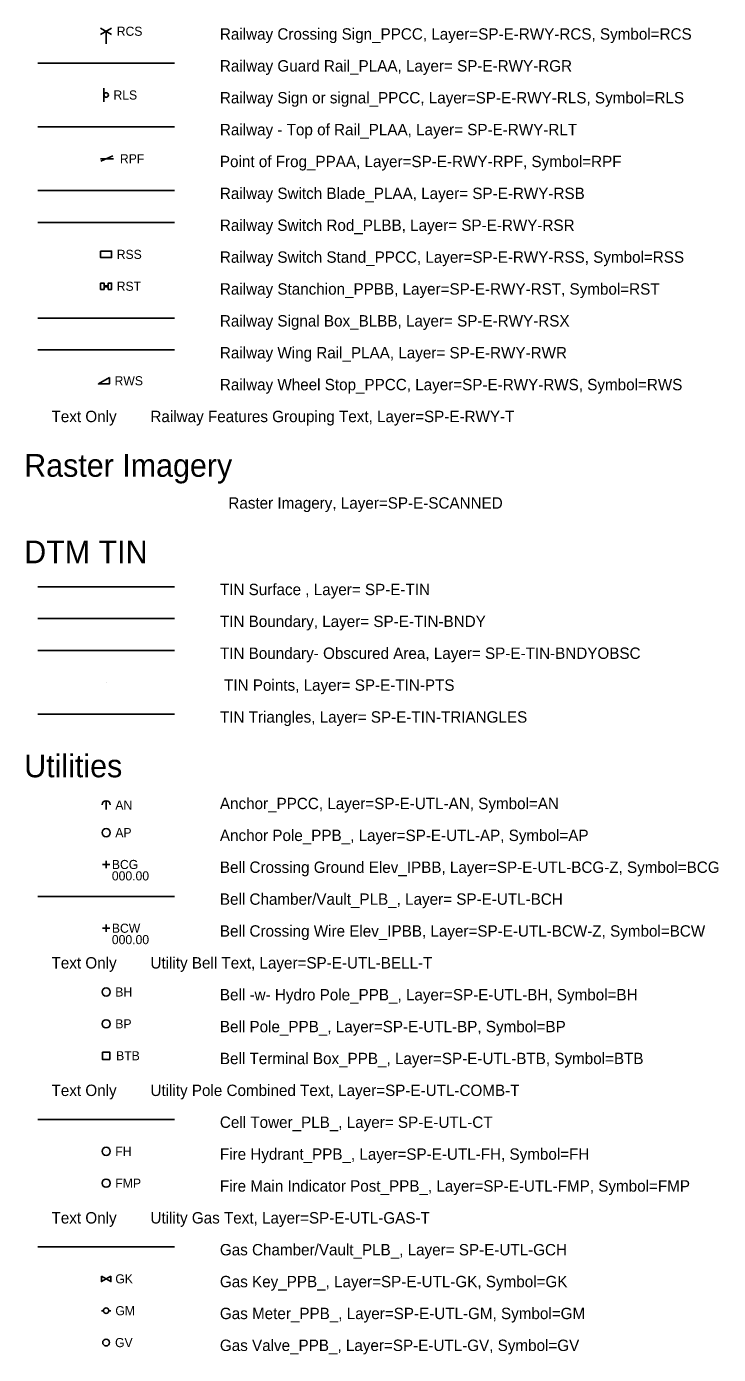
# Model space of a CAD drawing. Extents: x 500528 to 502626, y 4210261 to 4212624.
# Drawn here: x 501384.1 to 501536.1, y 4211147 to 4211438.6 of the extents above; entities that cross this region are included whole.
import ezdxf

# ---------------------------------------------------------------- set-up
doc = ezdxf.new("R2010")
doc.units = 0
for name, color, linetype in [('Default', 7, 'Continuous'), ('SP-E-RWY-RCS', 7, 'Continuous'), ('SP-E-RWY-RGR', 7, 'Continuous'), ('SP-E-RWY-RLS', 7, 'Continuous'), ('SP-E-RWY-RLT', 7, 'Continuous'), ('SP-E-RWY-RPF', 7, 'Continuous'), ('SP-E-RWY-RSB', 7, 'Continuous'), ('SP-E-RWY-RSR', 7, 'Continuous'), ('SP-E-RWY-RSS', 7, 'Continuous'), ('SP-E-RWY-RST', 7, 'Continuous'), ('SP-E-RWY-RSX', 7, 'Continuous'), ('SP-E-RWY-RWR', 7, 'Continuous'), ('SP-E-RWY-RWS', 7, 'Continuous'), ('SP-E-RWY-T', 7, 'Continuous'), ('SP-E-SCANNED', 7, 'Continuous'), ('SP-E-TIN', 7, 'Continuous'), ('SP-E-TIN-BNDY', 7, 'Continuous'), ('SP-E-TIN-BNDYOBSC', 7, 'Continuous'), ('SP-E-TIN-PTS', 7, 'Continuous'), ('SP-E-TIN-TRIANGLES', 7, 'Continuous'), ('SP-E-UTL-AN', 7, 'Continuous'), ('SP-E-UTL-AP', 7, 'Continuous'), ('SP-E-UTL-BCG-Z', 7, 'Continuous'), ('SP-E-UTL-BCH', 7, 'Continuous'), ('SP-E-UTL-BCW-Z', 7, 'Continuous'), ('SP-E-UTL-BELL-T', 7, 'Continuous'), ('SP-E-UTL-BH', 7, 'Continuous'), ('SP-E-UTL-BP', 7, 'Continuous'), ('SP-E-UTL-BTB', 7, 'Continuous'), ('SP-E-UTL-COMB-T', 7, 'Continuous'), ('SP-E-UTL-CT', 7, 'Continuous'), ('SP-E-UTL-FH', 7, 'Continuous'), ('SP-E-UTL-FMP', 7, 'Continuous'), ('SP-E-UTL-GAS-T', 7, 'Continuous'), ('SP-E-UTL-GCH', 7, 'Continuous'), ('SP-E-UTL-GK', 7, 'Continuous'), ('SP-E-UTL-GM', 7, 'Continuous'), ('SP-E-UTL-GV', 7, 'Continuous'), ('SP-E-UTL-T', 7, 'Continuous')]:
    doc.layers.add(name, color=color, linetype=linetype)

# ---------------------------------------------------------------- blocks, each defined once
blk = doc.blocks.new('RCS')
at = {"layer": 'SP-E-RWY-RCS'}
for points in [[(-0.121, -0.07), (0.121, 0.07)], [(0.121, -0.07), (-0.121, 0.07)], [(0, 0), (0, -0.28)], [(0, 0), (0, 0)]]:
    blk.add_lwpolyline(points, dxfattribs=at)
at = {"layer": 'SP-E-RWY-T'}
blk.add_text('RCS', height=0.2, dxfattribs=at).set_placement((0.233, -0.1))
blk = doc.blocks.new('RLS')
at = {"layer": 'SP-E-RWY-RLS'}
for points in [[(-0.05, -0.15), (-0.05, 0.15)], [(0, 0), (0, 0)]]:
    blk.add_lwpolyline(points, dxfattribs=at)
blk.add_circle((0, 0), 0.0495, dxfattribs=at)
at = {"layer": 'SP-E-RWY-T'}
blk.add_text('RLS', height=0.2, dxfattribs=at).set_placement((0.161, -0.1))
blk = doc.blocks.new('RPF')
at = {"layer": 'SP-E-RWY-RPF'}
blk.add_line((-0.125, 0), (0.161, 0), dxfattribs=at)
blk.add_lwpolyline([(-0.114, -0.05), (0.148, 0.065)], dxfattribs=at)
at = {"layer": 'SP-E-RWY-T'}
blk.add_text('RPF', height=0.2, dxfattribs=at).set_placement((0.303, -0.1))
blk = doc.blocks.new('RSS')
at = {"layer": 'SP-E-RWY-RSS'}
blk.add_lwpolyline([(-0.121, 0.07), (-0.121, -0.07), (0.121, -0.07), (0.121, 0.07), (-0.121, 0.07)], dxfattribs=at)
at = {"layer": 'SP-E-RWY-T'}
blk.add_text('RSS', height=0.2, dxfattribs=at).set_placement((0.233, -0.1))
blk = doc.blocks.new('RST')
at = {"layer": 'SP-E-RWY-RST'}
blk.add_lwpolyline([(-0.121, 0.07), (-0.121, -0.07), (-0.046, -0.07), (-0.046, -0.01), (0.046, -0.01), (0.046, -0.07), (0.121, -0.07), (0.121, 0.07), (0.046, 0.07), (0.046, 0.01), (-0.046, 0.01), (-0.046, 0.07), (-0.121, 0.07)], dxfattribs=at)
at = {"layer": 'SP-E-RWY-T'}
blk.add_text('RST', height=0.2, dxfattribs=at).set_placement((0.233, -0.1))
blk = doc.blocks.new('RWS')
at = {"layer": 'SP-E-RWY-RWS'}
blk.add_lwpolyline([(0.073, 0.094), (-0.169, -0.046), (0.073, -0.046), (0.073, 0.094)], dxfattribs=at)
at = {"layer": 'SP-E-RWY-T'}
blk.add_text('RWS', height=0.2, dxfattribs=at).set_placement((0.185, -0.076))
blk = doc.blocks.new('POINT_DISPLAY')
at = {"layer": 'Default'}
blk.add_line((0, 0), (0, 0), dxfattribs=at)
blk = doc.blocks.new('AN')
at = {"layer": 'SP-E-UTL-AN'}
blk.add_lwpolyline([(0, -0.19), (0, 0)], dxfattribs=at)
blk.add_arc((0, -0.09), 0.09, 360, 180, dxfattribs=at)
at = {"layer": 'SP-E-UTL-T'}
blk.add_text('AN', height=0.2, dxfattribs=at).set_placement((0.202, -0.195))
blk = doc.blocks.new('AP')
at = {"layer": 'SP-E-UTL-AP'}
blk.add_lwpolyline([(0, 0), (0, 0)], dxfattribs=at)
blk.add_circle((0, 0), 0.09, dxfattribs=at)
at = {"layer": 'SP-E-UTL-T'}
blk.add_text('AP', height=0.2, dxfattribs=at).set_placement((0.202, -0.1))
blk = doc.blocks.new('BCG')
at = {"layer": 'SP-E-UTL-BCG-Z'}
for points in [[(-0.08, 0), (0.08, 0)], [(0, -0.08), (0, 0.08)]]:
    blk.add_lwpolyline(points, dxfattribs=at)
at = {"layer": 'SP-E-UTL-BELL-T'}
for s, p in [('BCG', (0.126, -0.1)), ('000.00', (0.126, -0.35))]:
    blk.add_text(s, height=0.2, dxfattribs=at).set_placement(p)
blk = doc.blocks.new('BCW')
at = {"layer": 'SP-E-UTL-BCW-Z'}
for points in [[(-0.08, 0), (0.08, 0)], [(0, -0.08), (0, 0.08)]]:
    blk.add_lwpolyline(points, dxfattribs=at)
at = {"layer": 'SP-E-UTL-BELL-T'}
for s, p in [('BCW', (0.126, -0.1)), ('000.00', (0.126, -0.35))]:
    blk.add_text(s, height=0.2, dxfattribs=at).set_placement(p)
blk = doc.blocks.new('BH')
at = {"layer": 'SP-E-UTL-BH'}
blk.add_lwpolyline([(0, 0), (0, 0)], dxfattribs=at)
blk.add_circle((0, 0), 0.09, dxfattribs=at)
at = {"layer": 'SP-E-UTL-COMB-T'}
blk.add_text('BH', height=0.2, dxfattribs=at).set_placement((0.202, -0.1))
blk = doc.blocks.new('BP')
at = {"layer": 'SP-E-UTL-BP'}
blk.add_lwpolyline([(0, 0), (0, 0)], dxfattribs=at)
blk.add_circle((0, 0), 0.09, dxfattribs=at)
at = {"layer": 'SP-E-UTL-BELL-T'}
blk.add_text('BP', height=0.2, dxfattribs=at).set_placement((0.202, -0.1))
blk = doc.blocks.new('BTB')
at = {"layer": 'SP-E-UTL-BTB'}
for points in [[(-0.08, 0.08), (-0.08, -0.08), (0.08, -0.08), (0.08, 0.08), (-0.08, 0.08)], [(0, 0), (0, 0)]]:
    blk.add_lwpolyline(points, dxfattribs=at)
at = {"layer": 'SP-E-UTL-BELL-T'}
blk.add_text('BTB', height=0.2, dxfattribs=at).set_placement((0.22, -0.1))
blk = doc.blocks.new('FH')
at = {"layer": 'SP-E-UTL-FH'}
blk.add_lwpolyline([(0, 0), (0, 0)], dxfattribs=at)
blk.add_circle((0, 0), 0.09, dxfattribs=at)
at = {"layer": 'SP-E-UTL-T'}
blk.add_text('FH', height=0.2, dxfattribs=at).set_placement((0.202, -0.1))
blk = doc.blocks.new('FMP')
at = {"layer": 'SP-E-UTL-FMP'}
blk.add_lwpolyline([(0, 0), (0, 0)], dxfattribs=at)
blk.add_circle((0, 0), 0.09, dxfattribs=at)
at = {"layer": 'SP-E-UTL-T'}
blk.add_text('FMP', height=0.2, dxfattribs=at).set_placement((0.202, -0.1))
blk = doc.blocks.new('GK')
at = {"layer": 'SP-E-UTL-GK'}
for points in [[(-0.104, 0.06), (-0.104, -0.06), (0, 0), (-0.104, 0.06)], [(0.104, 0.06), (0.104, -0.06), (0, 0), (0.104, 0.06)]]:
    blk.add_lwpolyline(points, dxfattribs=at)
at = {"layer": 'SP-E-UTL-GAS-T'}
blk.add_text('GK', height=0.2, dxfattribs=at).set_placement((0.202, -0.1))
blk = doc.blocks.new('GM')
at = {"layer": 'SP-E-UTL-GM'}
for p, q in [((-0.06, 0), (-0.104, 0)), ((0.104, 0), (0.06, 0))]:
    blk.add_line(p, q, dxfattribs=at)
blk.add_circle((0, 0), 0.06, dxfattribs=at)
at = {"layer": 'SP-E-UTL-GAS-T'}
blk.add_text('GM', height=0.2, dxfattribs=at).set_placement((0.202, -0.1))
blk = doc.blocks.new('GV')
at = {"layer": 'SP-E-UTL-GV'}
blk.add_lwpolyline([(0, 0), (0, 0)], dxfattribs=at)
blk.add_circle((0, 0), 0.075, dxfattribs=at)
at = {"layer": 'SP-E-UTL-GAS-T'}
blk.add_text('GV', height=0.2, dxfattribs=at).set_placement((0.196, -0.1))

msp = doc.modelspace()

# ---------------------------------------------------------------- linework, layer by layer
at = {"layer": 'SP-E-RWY-RGR'}
msp.add_line((501386.55, 4211430.59), (501416.55, 4211430.59), dxfattribs=at)
at = {"layer": 'SP-E-RWY-RLT'}
msp.add_line((501386.55, 4211416.59), (501416.55, 4211416.59), dxfattribs=at)
at = {"layer": 'SP-E-RWY-RSB'}
msp.add_line((501386.55, 4211402.59), (501416.55, 4211402.59), dxfattribs=at)
at = {"layer": 'SP-E-RWY-RSR'}
msp.add_line((501386.55, 4211395.59), (501416.55, 4211395.59), dxfattribs=at)
at = {"layer": 'SP-E-RWY-RSX'}
msp.add_line((501386.55, 4211374.59), (501416.55, 4211374.59), dxfattribs=at)
at = {"layer": 'SP-E-RWY-RWR'}
msp.add_line((501386.55, 4211367.59), (501416.55, 4211367.59), dxfattribs=at)
at = {"layer": 'SP-E-TIN'}
msp.add_line((501386.55, 4211315.59), (501416.55, 4211315.59), dxfattribs=at)
at = {"layer": 'SP-E-TIN-BNDY'}
msp.add_line((501386.55, 4211308.59), (501416.55, 4211308.59), dxfattribs=at)
at = {"layer": 'SP-E-TIN-BNDYOBSC'}
msp.add_line((501386.55, 4211301.59), (501416.55, 4211301.59), dxfattribs=at)
at = {"layer": 'SP-E-TIN-TRIANGLES'}
msp.add_line((501386.55, 4211287.59), (501416.55, 4211287.59), dxfattribs=at)
at = {"layer": 'SP-E-UTL-BCH'}
msp.add_line((501386.55, 4211247.59), (501416.55, 4211247.59), dxfattribs=at)
at = {"layer": 'SP-E-UTL-CT'}
msp.add_line((501386.55, 4211198.59), (501416.55, 4211198.59), dxfattribs=at)
at = {"layer": 'SP-E-UTL-GCH'}
msp.add_line((501386.55, 4211170.59), (501416.55, 4211170.59), dxfattribs=at)

# ---------------------------------------------------------------- block references
at = {"layer": 'SP-E-RWY-RCS', "xscale": 10, "yscale": 10}
msp.add_blockref('RCS', (501401.55, 4211437.59), dxfattribs=at)
at = {"layer": 'SP-E-RWY-RLS', "xscale": 10, "yscale": 10}
msp.add_blockref('RLS', (501401.55, 4211423.59), dxfattribs=at)
at = {"layer": 'SP-E-RWY-RPF', "xscale": 10, "yscale": 10}
msp.add_blockref('RPF', (501401.55, 4211409.59), dxfattribs=at)
at = {"layer": 'SP-E-RWY-RSS', "xscale": 10, "yscale": 10}
msp.add_blockref('RSS', (501401.55, 4211388.59), dxfattribs=at)
at = {"layer": 'SP-E-RWY-RST', "xscale": 10, "yscale": 10}
msp.add_blockref('RST', (501401.55, 4211381.59), dxfattribs=at)
at = {"layer": 'SP-E-RWY-RWS', "xscale": 10, "yscale": 10}
msp.add_blockref('RWS', (501401.55, 4211360.59), dxfattribs=at)
at = {"layer": 'SP-E-TIN-PTS', "xscale": 10, "yscale": 10}
msp.add_blockref('POINT_DISPLAY', (501401.55, 4211294.59), dxfattribs=at)
at = {"layer": 'SP-E-UTL-AN', "xscale": 10, "yscale": 10}
msp.add_blockref('AN', (501401.55, 4211268.59), dxfattribs=at)
at = {"layer": 'SP-E-UTL-AP', "xscale": 10, "yscale": 10}
msp.add_blockref('AP', (501401.55, 4211261.59), dxfattribs=at)
at = {"layer": 'SP-E-UTL-BCG-Z', "xscale": 10, "yscale": 10}
msp.add_blockref('BCG', (501401.55, 4211254.59), dxfattribs=at)
at = {"layer": 'SP-E-UTL-BCW-Z', "xscale": 10, "yscale": 10}
msp.add_blockref('BCW', (501401.55, 4211240.59), dxfattribs=at)
at = {"layer": 'SP-E-UTL-BH', "xscale": 10, "yscale": 10}
msp.add_blockref('BH', (501401.55, 4211226.59), dxfattribs=at)
at = {"layer": 'SP-E-UTL-BP', "xscale": 10, "yscale": 10}
msp.add_blockref('BP', (501401.55, 4211219.59), dxfattribs=at)
at = {"layer": 'SP-E-UTL-BTB', "xscale": 10, "yscale": 10}
msp.add_blockref('BTB', (501401.55, 4211212.59), dxfattribs=at)
at = {"layer": 'SP-E-UTL-FH', "xscale": 10, "yscale": 10}
msp.add_blockref('FH', (501401.55, 4211191.59), dxfattribs=at)
at = {"layer": 'SP-E-UTL-FMP', "xscale": 10, "yscale": 10}
msp.add_blockref('FMP', (501401.55, 4211184.59), dxfattribs=at)
at = {"layer": 'SP-E-UTL-GK', "xscale": 10, "yscale": 10}
msp.add_blockref('GK', (501401.55, 4211163.59), dxfattribs=at)
at = {"layer": 'SP-E-UTL-GM', "xscale": 10, "yscale": 10}
msp.add_blockref('GM', (501401.55, 4211156.59), dxfattribs=at)
at = {"layer": 'SP-E-UTL-GV', "xscale": 10, "yscale": 10}
msp.add_blockref('GV', (501401.55, 4211149.59), dxfattribs=at)

# ---------------------------------------------------------------- texts
at = {"layer": 'Default'}
for s, p in [('Raster Imagery ', (501383.55, 4211339.74)), ('DTM TIN ', (501383.55, 4211320.74)), ('Utilities ', (501383.55, 4211273.74))]:
    msp.add_text(s, height=5, dxfattribs=at).set_placement(p)
at = {"layer": 'SP-E-RWY-RCS'}
msp.add_text('Railway Crossing Sign_PPCC, Layer=SP-E-RWY-RCS, Symbol=RCS ', height=2.5, dxfattribs=at).set_placement((501426.55, 4211435.74))
at = {"layer": 'SP-E-RWY-RGR'}
msp.add_text('Railway Guard Rail_PLAA, Layer= SP-E-RWY-RGR ', height=2.5, dxfattribs=at).set_placement((501426.55, 4211428.74))
at = {"layer": 'SP-E-RWY-RLS'}
msp.add_text('Railway Sign or signal_PPCC, Layer=SP-E-RWY-RLS, Symbol=RLS ', height=2.5, dxfattribs=at).set_placement((501426.55, 4211421.74))
at = {"layer": 'SP-E-RWY-RLT'}
msp.add_text('Railway - Top of Rail_PLAA, Layer= SP-E-RWY-RLT ', height=2.5, dxfattribs=at).set_placement((501426.55, 4211414.74))
at = {"layer": 'SP-E-RWY-RPF'}
msp.add_text('Point of Frog_PPAA, Layer=SP-E-RWY-RPF, Symbol=RPF ', height=2.5, dxfattribs=at).set_placement((501426.55, 4211407.74))
at = {"layer": 'SP-E-RWY-RSB'}
msp.add_text('Railway Switch Blade_PLAA, Layer= SP-E-RWY-RSB ', height=2.5, dxfattribs=at).set_placement((501426.55, 4211400.74))
at = {"layer": 'SP-E-RWY-RSR'}
msp.add_text('Railway Switch Rod_PLBB, Layer= SP-E-RWY-RSR ', height=2.5, dxfattribs=at).set_placement((501426.55, 4211393.74))
at = {"layer": 'SP-E-RWY-RSS'}
msp.add_text('Railway Switch Stand_PPCC, Layer=SP-E-RWY-RSS, Symbol=RSS ', height=2.5, dxfattribs=at).set_placement((501426.55, 4211386.74))
at = {"layer": 'SP-E-RWY-RST'}
msp.add_text('Railway Stanchion_PPBB, Layer=SP-E-RWY-RST, Symbol=RST ', height=2.5, dxfattribs=at).set_placement((501426.55, 4211379.74))
at = {"layer": 'SP-E-RWY-RSX'}
msp.add_text('Railway Signal Box_BLBB, Layer= SP-E-RWY-RSX ', height=2.5, dxfattribs=at).set_placement((501426.55, 4211372.74))
at = {"layer": 'SP-E-RWY-RWR'}
msp.add_text('Railway Wing Rail_PLAA, Layer= SP-E-RWY-RWR ', height=2.5, dxfattribs=at).set_placement((501426.55, 4211365.74))
at = {"layer": 'SP-E-RWY-RWS'}
msp.add_text('Railway Wheel Stop_PPCC, Layer=SP-E-RWY-RWS, Symbol=RWS ', height=2.5, dxfattribs=at).set_placement((501426.55, 4211358.74))
at = {"layer": 'SP-E-RWY-T'}
msp.add_text('Text Only        Railway Features Grouping Text, Layer=SP-E-RWY-T', height=2.5, dxfattribs=at).set_placement((501389.55, 4211351.74))
at = {"layer": 'SP-E-SCANNED'}
msp.add_text('  Raster Imagery, Layer=SP-E-SCANNED ', height=2.5, dxfattribs=at).set_placement((501426.55, 4211332.74))
at = {"layer": 'SP-E-TIN'}
msp.add_text('TIN Surface , Layer= SP-E-TIN ', height=2.5, dxfattribs=at).set_placement((501426.55, 4211313.74))
at = {"layer": 'SP-E-TIN-BNDY'}
msp.add_text('TIN Boundary, Layer= SP-E-TIN-BNDY ', height=2.5, dxfattribs=at).set_placement((501426.55, 4211306.74))
at = {"layer": 'SP-E-TIN-BNDYOBSC'}
msp.add_text('TIN Boundary- Obscured Area, Layer= SP-E-TIN-BNDYOBSC ', height=2.5, dxfattribs=at).set_placement((501426.55, 4211299.74))
at = {"layer": 'SP-E-TIN-PTS'}
msp.add_text(' TIN Points, Layer= SP-E-TIN-PTS ', height=2.5, dxfattribs=at).set_placement((501426.55, 4211292.74))
at = {"layer": 'SP-E-TIN-TRIANGLES'}
msp.add_text('TIN Triangles, Layer= SP-E-TIN-TRIANGLES ', height=2.5, dxfattribs=at).set_placement((501426.55, 4211285.74))
at = {"layer": 'SP-E-UTL-AN'}
msp.add_text('Anchor_PPCC, Layer=SP-E-UTL-AN, Symbol=AN ', height=2.5, dxfattribs=at).set_placement((501426.55, 4211266.74))
at = {"layer": 'SP-E-UTL-AP'}
msp.add_text('Anchor Pole_PPB_, Layer=SP-E-UTL-AP, Symbol=AP ', height=2.5, dxfattribs=at).set_placement((501426.55, 4211259.74))
at = {"layer": 'SP-E-UTL-BCG-Z'}
msp.add_text('Bell Crossing Ground Elev_IPBB, Layer=SP-E-UTL-BCG-Z, Symbol=BCG ', height=2.5, dxfattribs=at).set_placement((501426.55, 4211252.74))
at = {"layer": 'SP-E-UTL-BCH'}
msp.add_text('Bell Chamber/Vault_PLB_, Layer= SP-E-UTL-BCH ', height=2.5, dxfattribs=at).set_placement((501426.55, 4211245.74))
at = {"layer": 'SP-E-UTL-BCW-Z'}
msp.add_text('Bell Crossing Wire Elev_IPBB, Layer=SP-E-UTL-BCW-Z, Symbol=BCW ', height=2.5, dxfattribs=at).set_placement((501426.55, 4211238.74))
at = {"layer": 'SP-E-UTL-BELL-T'}
msp.add_text('Text Only        Utility Bell Text, Layer=SP-E-UTL-BELL-T', height=2.5, dxfattribs=at).set_placement((501389.55, 4211231.74))
at = {"layer": 'SP-E-UTL-BH'}
msp.add_text('Bell -w- Hydro Pole_PPB_, Layer=SP-E-UTL-BH, Symbol=BH ', height=2.5, dxfattribs=at).set_placement((501426.55, 4211224.74))
at = {"layer": 'SP-E-UTL-BP'}
msp.add_text('Bell Pole_PPB_, Layer=SP-E-UTL-BP, Symbol=BP ', height=2.5, dxfattribs=at).set_placement((501426.55, 4211217.74))
at = {"layer": 'SP-E-UTL-BTB'}
msp.add_text('Bell Terminal Box_PPB_, Layer=SP-E-UTL-BTB, Symbol=BTB ', height=2.5, dxfattribs=at).set_placement((501426.55, 4211210.74))
at = {"layer": 'SP-E-UTL-COMB-T'}
msp.add_text('Text Only        Utility Pole Combined Text, Layer=SP-E-UTL-COMB-T', height=2.5, dxfattribs=at).set_placement((501389.55, 4211203.74))
at = {"layer": 'SP-E-UTL-CT'}
msp.add_text('Cell Tower_PLB_, Layer= SP-E-UTL-CT ', height=2.5, dxfattribs=at).set_placement((501426.55, 4211196.74))
at = {"layer": 'SP-E-UTL-FH'}
msp.add_text('Fire Hydrant_PPB_, Layer=SP-E-UTL-FH, Symbol=FH ', height=2.5, dxfattribs=at).set_placement((501426.55, 4211189.74))
at = {"layer": 'SP-E-UTL-FMP'}
msp.add_text('Fire Main Indicator Post_PPB_, Layer=SP-E-UTL-FMP, Symbol=FMP ', height=2.5, dxfattribs=at).set_placement((501426.55, 4211182.74))
at = {"layer": 'SP-E-UTL-GAS-T'}
msp.add_text('Text Only        Utility Gas Text, Layer=SP-E-UTL-GAS-T', height=2.5, dxfattribs=at).set_placement((501389.55, 4211175.74))
at = {"layer": 'SP-E-UTL-GCH'}
msp.add_text('Gas Chamber/Vault_PLB_, Layer= SP-E-UTL-GCH ', height=2.5, dxfattribs=at).set_placement((501426.55, 4211168.74))
at = {"layer": 'SP-E-UTL-GK'}
msp.add_text('Gas Key_PPB_, Layer=SP-E-UTL-GK, Symbol=GK ', height=2.5, dxfattribs=at).set_placement((501426.55, 4211161.74))
at = {"layer": 'SP-E-UTL-GM'}
msp.add_text('Gas Meter_PPB_, Layer=SP-E-UTL-GM, Symbol=GM ', height=2.5, dxfattribs=at).set_placement((501426.55, 4211154.74))
at = {"layer": 'SP-E-UTL-GV'}
msp.add_text('Gas Valve_PPB_, Layer=SP-E-UTL-GV, Symbol=GV ', height=2.5, dxfattribs=at).set_placement((501426.55, 4211147.74))

doc.saveas('drawing.dxf')
